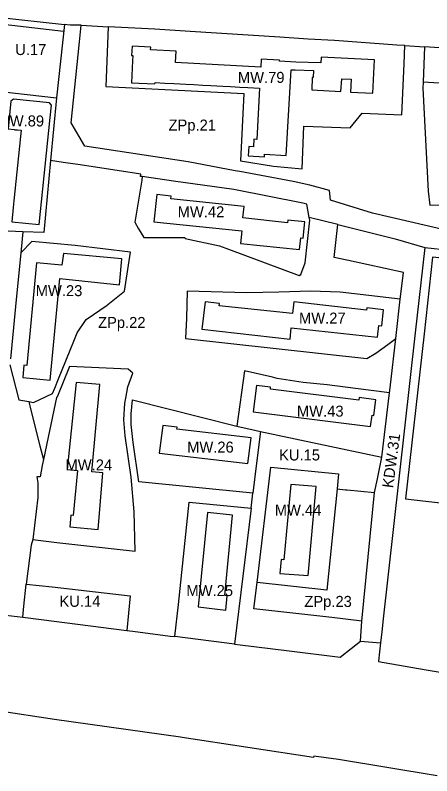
# Model space of a CAD drawing. Extents: x 7424434 to 7425898, y 5541432 to 5542659.
# Drawn here: x 7424804.8 to 7424993.9, y 5541504.3 to 5541849.5 of the extents above; entities that cross this region are included whole.
import ezdxf

# ---------------------------------------------------------------- set-up
doc = ezdxf.new("R2010")
doc.units = 0
for name, color, linetype in [('linie rozgraniczające', 7, 'Continuous'), ('nieprzekraczalne linie zabudowy', 7, 'Continuous'), ('obowiazujace linie zabudowy', 7, 'Continuous'), ('przeznaczenia terenów', 7, 'Continuous')]:
    doc.layers.add(name, color=color, linetype=linetype)

msp = doc.modelspace()

# ---------------------------------------------------------------- linework, layer by layer
at = {"layer": 'linie rozgraniczające'}
for p, q in [((7424788.7, 5541849.47), (7424827.16, 5541845.27)), ((7424827.16, 5541845.27), (7424823.5, 5541812)), ((7424829.73, 5541844.98), (7424827.16, 5541845.27)), ((7424834.72, 5541844.88), (7424829.73, 5541844.98)), ((7424833.94, 5541837.36), (7424834.72, 5541844.88)), ((7424834.72, 5541844.88), (7424846.95, 5541844.27)), ((7424846.95, 5541844.27), (7424845.92, 5541817.16)), ((7424868.12, 5541843.09), (7424846.95, 5541844.27)), ((7424884.28, 5541842.12), (7424868.12, 5541843.09)), ((7424924.94, 5541839.55), (7424884.28, 5541842.12)), ((7424937.78, 5541838.59), (7424924.94, 5541839.55)), ((7424830.19, 5541800.65), (7424833.94, 5541837.36)), ((7424949.78, 5541837.93), (7424937.78, 5541838.59)), ((7424978.05, 5541835.94), (7424949.78, 5541837.93)), ((7424981.71, 5541835.71), (7424978.05, 5541835.94)), ((7424981.33, 5541827.35), (7424981.71, 5541835.71)), ((7424981.71, 5541835.71), (7424990.69, 5541835.14)), ((7424990.69, 5541835.14), (7424990.01, 5541819.09)), ((7425028.31, 5541832.6), (7424990.69, 5541835.14)), ((7424980.34, 5541804.27), (7424981.33, 5541827.35)), ((7424990.01, 5541819.09), (7424989.93, 5541816.35)), ((7425028.52, 5541816.75), (7424990.01, 5541819.09)), ((7424796.69, 5541814.95), (7424823.5, 5541811.99)), ((7424845.92, 5541817.16), (7424908.6, 5541813.96)), ((7424989.93, 5541816.35), (7424992.23, 5541769.63)), ((7424823.5, 5541812), (7424820.87, 5541783.52)), ((7424908.6, 5541813.96), (7424907.03, 5541783.31)), ((7424956.85, 5541798.4), (7424962.33, 5541805)), ((7424962.33, 5541805), (7424980.34, 5541804.27)), ((7424836.47, 5541790.04), (7424830.19, 5541800.65)), ((7424935.43, 5541787.51), (7424935.88, 5541799.06)), ((7424935.88, 5541799.06), (7424956.85, 5541798.4)), ((7424883.33, 5541782.95), (7424836.47, 5541790.04)), ((7424935.13, 5541779.73), (7424935.43, 5541787.51)), ((7424820.87, 5541783.52), (7424817.85, 5541750.82)), ((7424826.61, 5541782.66), (7424820.87, 5541783.52)), ((7424833.25, 5541781.65), (7424826.61, 5541782.66)), ((7424841.18, 5541780.45), (7424833.25, 5541781.65)), ((7424861.79, 5541777.33), (7424841.18, 5541780.45)), ((7424904.72, 5541778.9), (7424883.33, 5541782.95)), ((7424907.03, 5541783.31), (7424922.14, 5541780.92)), ((7424922.14, 5541780.92), (7424935.13, 5541779.73)), ((7424861.64, 5541776.33), (7424861.79, 5541777.33)), ((7424906.73, 5541778.52), (7424904.72, 5541778.9)), ((7424931.01, 5541773.94), (7424906.73, 5541778.52)), ((7424862.23, 5541774.61), (7424859.15, 5541755.47)), ((7424862.49, 5541776.21), (7424861.64, 5541776.33)), ((7424862.49, 5541776.21), (7424862.23, 5541774.61)), ((7424876.68, 5541774.12), (7424862.49, 5541776.21)), ((7424903.99, 5541770.44), (7424876.68, 5541774.12)), ((7424938.56, 5541772.31), (7424931.01, 5541773.94)), ((7424935.39, 5541764.16), (7424903.99, 5541770.44)), ((7424947.56, 5541769.87), (7424938.56, 5541772.31)), ((7424948.01, 5541765.48), (7424947.56, 5541769.87)), ((7424992.23, 5541769.63), (7424993.02, 5541763.29)), ((7424937.24, 5541763.75), (7424935.39, 5541764.16)), ((7424938.29, 5541757.66), (7424937.24, 5541763.75)), ((7424967.07, 5541759.6), (7424948.01, 5541765.48)), ((7424993.02, 5541763.29), (7425023, 5541764.15)), ((7424936.45, 5541737.13), (7424938.51, 5541756.4)), ((7424938.51, 5541756.4), (7424938.29, 5541757.66)), ((7424951.21, 5541754.46), (7424938.29, 5541757.66)), ((7425001, 5541751.75), (7424967.07, 5541759.6)), ((7424859.15, 5541755.47), (7424860.84, 5541752.47)), ((7424949.68, 5541739.53), (7424951.21, 5541754.46)), ((7424951.21, 5541754.46), (7424977.37, 5541747.98)), ((7424808.23, 5541751.19), (7424798.21, 5541751.57)), ((7424808.23, 5541751.19), (7424807.48, 5541743.13)), ((7424817.85, 5541750.82), (7424808.23, 5541751.19)), ((7424860.84, 5541752.47), (7424863.14, 5541748.58)), ((7424812.4, 5541746.74), (7424807.32, 5541741.56)), ((7424832.09, 5541744.93), (7424812.4, 5541746.74)), ((7424863.14, 5541748.58), (7424881.78, 5541748.63)), ((7424881.78, 5541748.63), (7424881.98, 5541748.06)), ((7424881.98, 5541748.06), (7424897.54, 5541744.78)), ((7424977.37, 5541747.98), (7424990.77, 5541744.06)), ((7424807.48, 5541743.13), (7424807.32, 5541741.56)), ((7424857.16, 5541741.94), (7424832.09, 5541744.93)), ((7424897.54, 5541744.78), (7424901.65, 5541743.32)), ((7424901.65, 5541743.32), (7424933.67, 5541731.28)), ((7424990.77, 5541744.06), (7424986.44, 5541705.3)), ((7424990.77, 5541744.06), (7425022.36, 5541740.71)), ((7424807.32, 5541741.56), (7424804.86, 5541717.21)), ((7424854.42, 5541724.16), (7424857.16, 5541741.94)), ((7424956.1, 5541738.14), (7424949.68, 5541739.53)), ((7424934.48, 5541731.8), (7424936.45, 5541737.13)), ((7424981.03, 5541732.72), (7424956.1, 5541738.14)), ((7424979.91, 5541722.8), (7424981.03, 5541732.72)), ((7424933.67, 5541731.28), (7424934.48, 5541731.8)), ((7424846.82, 5541718.18), (7424854.42, 5541724.16)), ((7424882.87, 5541724.29), (7424882.51, 5541711.98)), ((7424910, 5541723.52), (7424882.87, 5541724.29)), ((7424924.44, 5541723.84), (7424910, 5541723.52)), ((7424939.03, 5541724.16), (7424924.44, 5541723.84)), ((7424952.37, 5541723.74), (7424939.03, 5541724.16)), ((7424965.37, 5541722.28), (7424952.37, 5541723.74)), ((7424979.66, 5541720.65), (7424965.37, 5541722.28)), ((7424979.66, 5541720.65), (7424979.91, 5541722.8)), ((7424977.6, 5541702.82), (7424979.66, 5541720.65)), ((7424804.86, 5541717.21), (7424802.63, 5541693.48)), ((7424837.01, 5541711.3), (7424846.49, 5541717.92)), ((7424846.49, 5541717.92), (7424846.82, 5541718.18)), ((7424882.51, 5541711.98), (7424882.19, 5541702.75)), ((7424833, 5541705.32), (7424837.01, 5541711.3)), ((7424831.47, 5541701.59), (7424833, 5541705.32)), ((7424986.44, 5541705.3), (7424971.79, 5541574.17)), ((7424824.51, 5541684.51), (7424831.47, 5541701.59)), ((7424882.19, 5541702.75), (7424964.43, 5541693.6)), ((7424973.94, 5541699.99), (7424977.6, 5541702.82)), ((7424975.01, 5541680.42), (7424977.6, 5541702.82)), ((7424968.49, 5541696.12), (7424973.94, 5541699.99)), ((7424964.43, 5541693.6), (7424968.49, 5541696.12)), ((7424802.41, 5541690.77), (7424806.44, 5541674.91)), ((7424829.5, 5541689.98), (7424823.96, 5541676.53)), ((7424856.07, 5541688.84), (7424829.5, 5541689.98)), ((7424858.16, 5541686.96), (7424856.07, 5541688.84)), ((7424908.85, 5541688.14), (7424905.41, 5541662.93)), ((7424921.63, 5541685.22), (7424908.85, 5541688.14)), ((7424822.75, 5541680.23), (7424824.51, 5541684.51)), ((7424855.94, 5541680.78), (7424858.16, 5541686.96)), ((7424923.81, 5541684.54), (7424921.63, 5541685.22)), ((7424935.49, 5541682.83), (7424923.81, 5541684.54)), ((7424854.97, 5541675.61), (7424855.94, 5541680.78)), ((7424946.44, 5541681.73), (7424935.49, 5541682.83)), ((7424959.34, 5541680.07), (7424946.44, 5541681.73)), ((7424974.74, 5541678.11), (7424975.01, 5541680.42)), ((7424813.03, 5541673.7), (7424821.76, 5541677.82)), ((7424821.76, 5541677.82), (7424822.75, 5541680.23)), ((7424974.74, 5541678.11), (7424959.34, 5541680.07)), ((7424971.32, 5541648.89), (7424974.74, 5541678.11)), ((7424806.44, 5541674.91), (7424810.91, 5541674.09)), ((7424810.91, 5541674.09), (7424813.03, 5541673.7)), ((7424810.91, 5541674.09), (7424811.73, 5541670.87)), ((7424823.56, 5541675.96), (7424819.79, 5541658)), ((7424823.96, 5541676.53), (7424823.56, 5541675.96)), ((7424854.54, 5541673.32), (7424854.97, 5541675.61)), ((7424857.4, 5541668.62), (7424858, 5541674.84)), ((7424858, 5541674.84), (7424905.41, 5541662.93)), ((7424811.73, 5541670.87), (7424816.02, 5541654.02)), ((7424854.08, 5541665.86), (7424854.54, 5541673.32)), ((7424857.45, 5541663.77), (7424857.4, 5541668.62)), ((7424854.68, 5541658.54), (7424854.08, 5541665.86)), ((7424858.38, 5541655.48), (7424857.45, 5541663.77)), ((7424905.41, 5541662.93), (7424914.19, 5541660.99)), ((7424914.19, 5541660.99), (7424916.12, 5541660.58)), ((7424916.12, 5541660.58), (7424914.38, 5541646.19)), ((7424916.12, 5541660.58), (7424971.32, 5541648.89)), ((7424819.79, 5541658), (7424817.59, 5541647.87)), ((7424857.39, 5541639.81), (7424854.68, 5541658.54)), ((7424816.02, 5541654.02), (7424817.59, 5541647.87)), ((7424860.91, 5541637.76), (7424858.38, 5541655.48)), ((7424817.59, 5541647.87), (7424816.97, 5541645.04)), ((7424914.38, 5541646.19), (7424912.72, 5541632.49)), ((7424969.23, 5541639.01), (7424971.32, 5541648.89)), ((7424816.97, 5541645.04), (7424816.17, 5541639.93)), ((7424914.58, 5541591.96), (7424920.79, 5541644.39)), ((7424920.79, 5541644.39), (7424951.63, 5541641.34)), ((7424816.17, 5541639.93), (7424814.63, 5541640)), ((7424814.63, 5541640), (7424814.99, 5541637.28)), ((7424858.76, 5541624.08), (7424857.39, 5541639.81)), ((7424951.63, 5541641.34), (7424950.94, 5541634.49)), ((7424967.92, 5541632.81), (7424969.23, 5541639.01)), ((7424814.99, 5541637.28), (7424815.12, 5541630.6)), ((7424912.72, 5541632.49), (7424860.91, 5541637.76)), ((7424911.86, 5541625.73), (7424912.72, 5541632.49)), ((7424950.94, 5541634.49), (7424946.3, 5541588.55)), ((7424950.94, 5541634.49), (7424954.69, 5541634.11)), ((7424954.69, 5541634.11), (7424955.46, 5541634.04)), ((7424955.46, 5541634.04), (7424967.92, 5541632.81)), ((7424962.16, 5541574.53), (7424967.92, 5541632.81)), ((7424815.12, 5541630.6), (7424812.87, 5541611.49)), ((7424878.88, 5541582.07), (7424883.83, 5541628.49)), ((7424883.83, 5541628.49), (7424911.86, 5541625.73)), ((7424911.86, 5541625.73), (7424904.43, 5541564.07)), ((7424859.3, 5541606.17), (7424858.76, 5541624.08)), ((7424812.87, 5541611.49), (7424811.98, 5541609.01)), ((7424812.87, 5541611.49), (7424823.75, 5541610.14)), ((7424811.98, 5541609.01), (7424809.73, 5541591.22)), ((7424823.75, 5541610.14), (7424859.3, 5541606.17)), ((7424808.76, 5541581.19), (7424809.73, 5541591.22)), ((7424809.73, 5541591.22), (7424821.52, 5541590.08)), ((7424913.14, 5541580.1), (7424914.58, 5541591.96)), ((7424946.3, 5541588.55), (7424914.58, 5541591.96)), ((7424821.52, 5541590.08), (7424856.96, 5541586.01)), ((7424856.96, 5541586.01), (7424855.43, 5541570.25)), ((7424808.28, 5541576.21), (7424808.76, 5541581.19)), ((7424877.33, 5541567.44), (7424878.88, 5541582.07)), ((7424797.91, 5541577.42), (7424808.28, 5541576.21)), ((7424948.53, 5541576.08), (7424913.14, 5541580.1)), ((7424808.28, 5541576.21), (7424816.63, 5541575.24)), ((7424816.63, 5541575.24), (7424855.43, 5541570.25)), ((7424962.16, 5541574.53), (7424948.53, 5541576.08)), ((7424961.63, 5541565.38), (7424962.16, 5541574.53)), ((7424971.79, 5541574.17), (7424971.26, 5541569.41)), ((7424855.43, 5541570.25), (7424858.17, 5541569.9)), ((7424858.17, 5541569.9), (7424875.18, 5541567.71)), ((7424875.18, 5541567.71), (7424877.33, 5541567.44)), ((7424904.43, 5541564.07), (7424877.33, 5541567.44)), ((7424971.14, 5541568.33), (7424970.72, 5541564.61)), ((7424971.15, 5541568.41), (7424971.14, 5541568.33)), ((7424971.26, 5541569.41), (7424971.15, 5541568.41)), ((7424904.43, 5541564.07), (7424906.95, 5541563.76)), ((7424906.95, 5541563.76), (7424927.99, 5541561.15)), ((7424957.31, 5541562.05), (7424961.63, 5541565.38)), ((7424961.63, 5541565.38), (7424965.2, 5541565.08)), ((7424965.2, 5541565.08), (7424970.72, 5541564.61)), ((7424970.72, 5541564.61), (7424970.26, 5541560.49)), ((7424927.99, 5541561.15), (7424952.28, 5541558.19)), ((7424952.28, 5541558.19), (7424957.31, 5541562.05)), ((7424970.26, 5541560.49), (7424969.79, 5541556.24)), ((7424969.79, 5541556.24), (7424969.78, 5541556.19)), ((7424969.78, 5541556.19), (7424972.34, 5541555.74)), ((7424972.34, 5541555.74), (7424991.33, 5541552.3)), ((7424991.33, 5541552.3), (7425001.36, 5541550.71)), ((7424822.67, 5541529.85), (7424774.35, 5541537)), ((7424879.83, 5541521.82), (7424822.67, 5541529.85)), ((7424880.65, 5541521.7), (7424879.83, 5541521.82)), ((7424880.65, 5541521.69), (7424880.65, 5541521.7)), ((7424940.18, 5541512.52), (7424880.65, 5541521.69)), ((7424940.44, 5541513.2), (7424940.18, 5541512.52)), ((7424951.51, 5541511.66), (7424940.44, 5541513.2)), ((7424996.45, 5541504.28), (7424951.51, 5541511.66))]:
    msp.add_line(p, q, dxfattribs=at)
at = {"layer": 'nieprzekraczalne linie zabudowy'}
msp.add_line((7424826.72, 5541842.04), (7424788.53, 5541846.49), dxfattribs=at)
msp.add_lwpolyline([(7425106.17, 5541615.78), (7425109.27, 5541640.19), (7425119.48, 5541720.64), (7425120.2, 5541726.31), (7425118.52, 5541726.49), (7425101.66, 5541728.28), (7425085.31, 5541730.01), (7425077.8, 5541730.81), (7425070.41, 5541731.59), (7425062.25, 5541732.46), (7425060.26, 5541732.67), (7425021.94, 5541736.73), (7424994.3, 5541739.66), (7424990.42, 5541704.86), (7424982.04, 5541629.92)], close=True, dxfattribs=at)
at = {"layer": 'obowiazujace linie zabudowy'}
for points in [[(7424940.27, 5541824.33), (7424940.12, 5541821.25), (7424939.66, 5541821.27), (7424939.52, 5541815.56), (7424952.69, 5541814.81), (7424953.08, 5541820.66), (7424957.27, 5541820.38), (7424957.02, 5541814.53), (7424967.12, 5541814.02), (7424967.95, 5541829.24), (7424943.66, 5541830.38), (7424943.54, 5541827.85), (7424932.16, 5541828.17), (7424924.81, 5541828.59), (7424924.84, 5541829.03), (7424916.48, 5541829.51), (7424916.27, 5541825.93), (7424877.62, 5541828.03), (7424877.89, 5541833.1), (7424866.29, 5541833.73), (7424866.37, 5541834.9), (7424857.84, 5541835.43), (7424857.67, 5541831.25), (7424858.21, 5541831.23), (7424858.1, 5541828.72), (7424857.66, 5541818.85), (7424868.25, 5541818.31), (7424868.28, 5541818.92), (7424872.67, 5541818.69), (7424876.85, 5541818.47), (7424882.25, 5541818.23), (7424885.96, 5541818.04), (7424889.97, 5541817.77), (7424893.68, 5541817.58), (7424899.03, 5541817.27), (7424902.58, 5541817.08), (7424906.79, 5541816.85), (7424910.45, 5541816.66), (7424915.73, 5541816.39), (7424914.54, 5541793.06), (7424913.2, 5541793.14), (7424913, 5541789.71), (7424910.85, 5541789.83), (7424910.61, 5541785.59), (7424917.92, 5541785.17), (7424917.98, 5541786.36), (7424927.88, 5541785.79), (7424930.1, 5541824.75), (7424931.95, 5541824.65)], [(7424815.73, 5541754.48), (7424820.7, 5541803.05), (7424821.28, 5541808.59), (7424820.3, 5541809.73), (7424803.98, 5541811.34), (7424802.79, 5541810.42), (7424801.55, 5541797.91), (7424804.53, 5541797.63), (7424804.52, 5541797.49), (7424805.76, 5541797.39), (7424807.46, 5541797.25), (7424807.17, 5541794.47), (7424805.86, 5541781.32), (7424805.58, 5541778.41), (7424804.23, 5541765.22), (7424803.94, 5541762.25), (7424803.29, 5541755.69)], [(7424935.5, 5541748.3), (7424936.28, 5541755.72), (7424928.62, 5541756.52), (7424928.49, 5541755.31), (7424908.21, 5541757.44), (7424908.75, 5541762.64), (7424875.44, 5541766.14), (7424875.57, 5541767.41), (7424869.11, 5541768.09), (7424867.81, 5541755.76), (7424907.75, 5541751.57), (7424907.16, 5541745.91), (7424933.95, 5541743.11), (7424934.5, 5541748.4)], [(7424820.67, 5541683.79), (7424825.08, 5541729.97), (7424852.11, 5541727.09), (7424853.21, 5541738.83), (7424826.74, 5541741.31), (7424825.96, 5541736), (7424814.39, 5541737.1), (7424810.03, 5541690.47), (7424808.76, 5541690.59), (7424808.24, 5541685.04)], [(7424969.28, 5541703.33), (7424969.86, 5541708.69), (7424971.3, 5541708.53), (7424972.09, 5541715.78), (7424964.47, 5541716.6), (7424964.35, 5541715.56), (7424931.25, 5541719.37), (7424930.69, 5541714.03), (7424897.42, 5541717.55), (7424897.55, 5541718.65), (7424891.08, 5541719.45), (7424889.59, 5541706.96), (7424929.59, 5541702.51), (7424930.12, 5541707.52)], [(7424842.48, 5541615.99), (7424844.55, 5541641.8), (7424839.51, 5541642.2), (7424843.15, 5541681.91), (7424832.48, 5541682.75), (7424828.42, 5541643.29), (7424833.06, 5541642.78), (7424831.13, 5541622.44), (7424830.1, 5541622.53), (7424829.6, 5541617.28)], [(7424912.8, 5541669.43), (7424966.08, 5541662.86), (7424966.87, 5541667.96), (7424967.65, 5541667.84), (7424968.56, 5541674.97), (7424960.97, 5541675.9), (7424960.83, 5541674.79), (7424920.65, 5541679.69), (7424920.77, 5541680.72), (7424914.28, 5541681.38)], [(7424870.2, 5541650.72), (7424910.42, 5541645.98), (7424911.91, 5541657.59), (7424878.19, 5541661.58), (7424878.3, 5541662.47), (7424871.84, 5541663.23)], [(7424928.41, 5541620.2), (7424926.77, 5541602.34), (7424925.58, 5541602.45), (7424924.99, 5541596.07), (7424937.88, 5541595.14), (7424941.38, 5541635.61), (7424929.91, 5541636.52)], [(7424887.88, 5541580.98), (7424900.46, 5541579.47), (7424901.09, 5541586), (7424899.94, 5541586.11), (7424903.45, 5541622.49), (7424892.16, 5541623.76)]]:
    msp.add_lwpolyline(points, close=True, dxfattribs=at)

# ---------------------------------------------------------------- texts
at = {"layer": 'przeznaczenia terenów'}
for s, p in [('U.17', (7424804.79, 5541831.39)), ('MW.79', (7424905.9, 5541818.75)), ('MW.89', (7424796.73, 5541798.98)), ('ZPp.21', (7424874.4, 5541797.1)), ('MW.42', (7424878.55, 5541757.75)), ('MW.23', (7424814.09, 5541721.96)), ('ZPp.22', (7424842.4, 5541707.52)), ('MW.27', (7424933.64, 5541709.49)), ('MW.43', (7424932.71, 5541667.27)), ('MW.26', (7424882.85, 5541650.95)), ('KU.15', (7424924.61, 5541647.39)), ('MW.24', (7424827.63, 5541642.85)), ('MW.44', (7424922.64, 5541622.4)), ('MW.25', (7424882.52, 5541585.84)), ('KU.14', (7424824.88, 5541580.97)), ('ZPp.23', (7424936.08, 5541580.92))]:
    msp.add_text(s, height=5, dxfattribs=at).set_placement(p)
msp.add_text('KDW.31', height=5, rotation=82.3475, dxfattribs=at).set_placement((7424976.34, 5541634.67))

doc.saveas('drawing.dxf')
